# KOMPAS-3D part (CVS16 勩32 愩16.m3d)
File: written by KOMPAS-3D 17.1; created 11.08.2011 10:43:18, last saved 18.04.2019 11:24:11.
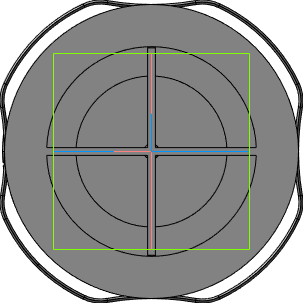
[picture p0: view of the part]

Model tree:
1. Плоскость XY
2. Плоскость ZX
3. Плоскость ZY
4. Ось X
5. Ось Y
6. Ось Z
7. Начало координат
8. Операция без истории:2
